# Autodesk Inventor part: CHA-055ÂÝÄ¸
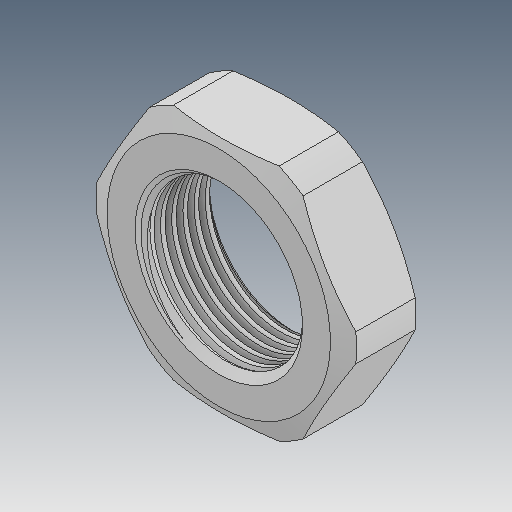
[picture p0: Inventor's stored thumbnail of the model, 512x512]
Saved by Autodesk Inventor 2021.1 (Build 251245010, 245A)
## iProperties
Created: 2019-05
Part Number: CHA-055ÂÝÄ¸
Material: Ogólny
Document SubType Name: Modeling
Designer: user
Density: 1 g/cm^3
Appearance: Domyślna
Author: user
Revision Number: ÈÎºÎ
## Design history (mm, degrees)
feature "¾µÏò1"
node "Bryła1"
